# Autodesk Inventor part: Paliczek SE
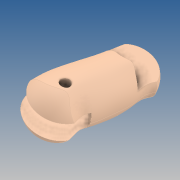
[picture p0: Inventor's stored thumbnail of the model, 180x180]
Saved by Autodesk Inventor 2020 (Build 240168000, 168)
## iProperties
Created: 2019-10
Part Number: Paliczek SE
Material: GFRP
Document SubType Name: Modeling
Designer: yello
Density: 1.75 g/cm^3
Appearance: Default
Author: yello
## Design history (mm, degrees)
feature "Paliczek SE"
sketch "Sketch1"
  geometry: C1 r 2 at (0, 0); 1 further point
  constraints: 1 centre point
  dimensions: "d0" = 4 diameter of C1
extrude "Extrusion1" cut sketch "Sketch1" stored distance "d1" = 100; taper "d2" = 0 deg
body "Solid1"
